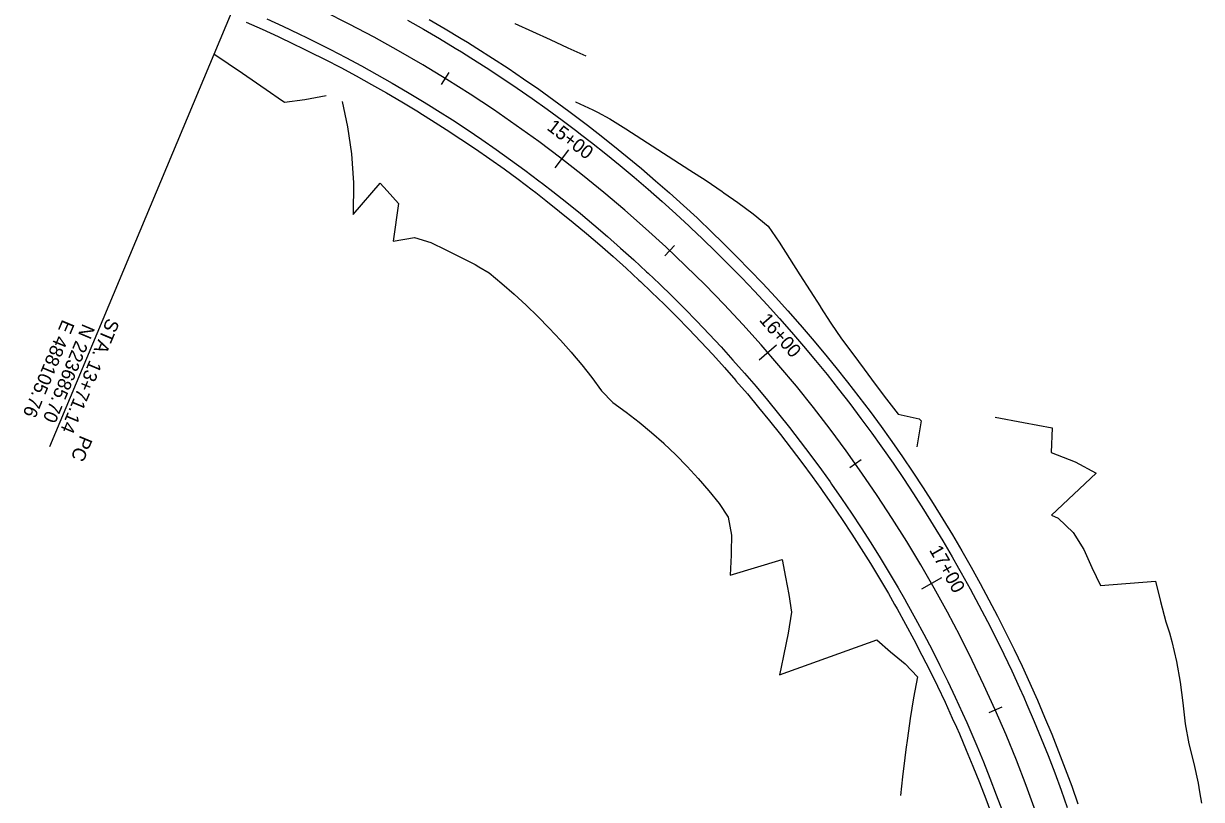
# Model space of a CAD drawing. Extents: x 487756 to 488722, y 222467 to 224000.
# Drawn here: x 488027.1 to 488442.7, y 223395.2 to 223669 of the extents above; entities that cross this region are included whole.
import ezdxf

# ---------------------------------------------------------------- set-up
doc = ezdxf.new("R2010")
doc.units = 0
for name, color, linetype in [('HM-SMOD-BRK LINE', 7, 'Continuous'), ('HR-FEAT-CUT', 7, 'Continuous'), ('HR-FEAT-EOR', 7, 'Continuous'), ('HR-FEAT-FILL', 7, 'Continuous'), ('HR-GMSC-HOR_VER ALN', 7, 'Continuous'), ('HR-GPLN-CL STA', 7, 'Continuous'), ('HR-GPLN-CL TICKS', 7, 'Continuous'), ('HR-GPLN-PCPT LDR', 7, 'Continuous'), ('HR-GPLN-PCPT TXT', 7, 'Continuous'), ('SV_MISC_MISC_TOPO', 7, 'Continuous')]:
    doc.layers.add(name, color=color, linetype=linetype)

msp = doc.modelspace()

# ---------------------------------------------------------------- linework, layer by layer
at = {"layer": 'HM-SMOD-BRK LINE'}
for points in [[(488112.92, 223670.6), (488118.58, 223668.02), (488124.21, 223665.36), (488127.22, 223663.91), (488129.8, 223662.64), (488135.35, 223659.84), (488140.87, 223656.97), (488146.35, 223654.04), (488151.8, 223651.03), (488157.21, 223647.95), (488162.57, 223644.81), (488167.9, 223641.59), (488170.02, 223640.29), (488173.18, 223638.31), (488178.43, 223634.97), (488183.63, 223631.55), (488188.78, 223628.08), (488193.89, 223624.53), (488198.96, 223620.92), (488203.98, 223617.25), (488208.95, 223613.51), (488210.24, 223612.52), (488213.87, 223609.71), (488218.75, 223605.85), (488223.58, 223601.92), (488228.35, 223597.94), (488233.08, 223593.89), (488237.75, 223589.79), (488242.37, 223585.62), (488246.94, 223581.4), (488247.5, 223580.88), (488251.45, 223577.12), (488255.91, 223572.78), (488260.31, 223568.39), (488264.66, 223563.94), (488268.95, 223559.44), (488273.18, 223554.88), (488277.35, 223550.26), (488281.4, 223545.67), (488281.47, 223545.6), (488285.52, 223540.88), (488289.51, 223536.12), (488293.45, 223531.3), (488297.32, 223526.43), (488301.13, 223521.51), (488304.88, 223516.55), (488308.56, 223511.53), (488311.63, 223507.26), (488312.18, 223506.48), (488315.73, 223501.37), (488319.22, 223496.22), (488322.65, 223491.03), (488326, 223485.79), (488329.29, 223480.51), (488332.52, 223475.2), (488335.67, 223469.83), (488337.86, 223466.01), (488338.76, 223464.43), (488341.78, 223459), (488344.72, 223453.52), (488347.6, 223448), (488350.41, 223442.45), (488353.15, 223436.87), (488355.81, 223431.25), (488358.41, 223425.6), (488359.85, 223422.36), (488360.93, 223419.91), (488363.38, 223414.19), (488365.76, 223408.44), (488368.06, 223402.67), (488370.29, 223396.86), (488372.44, 223391.03)], [(488162.56, 223670.22), (488168.21, 223667), (488173.82, 223663.72), (488179.38, 223660.36), (488181.59, 223659), (488184.9, 223656.93), (488190.38, 223653.44), (488195.82, 223649.87), (488201.2, 223646.23), (488206.54, 223642.53), (488211.84, 223638.76), (488217.08, 223634.92), (488222.28, 223631.01), (488223.63, 223629.98), (488227.43, 223627.04), (488232.52, 223623.01), (488237.56, 223618.91), (488242.55, 223614.74), (488247.49, 223610.51), (488252.37, 223606.22), (488257.2, 223601.87), (488261.98, 223597.46), (488262.56, 223596.91), (488266.69, 223592.99), (488271.35, 223588.45), (488275.95, 223583.86), (488280.49, 223579.21), (488284.97, 223574.51), (488289.4, 223569.74), (488293.76, 223564.92), (488297.99, 223560.12), (488298.06, 223560.05), (488302.29, 223555.12), (488306.47, 223550.14), (488310.58, 223545.1), (488314.62, 223540.01), (488318.61, 223534.88), (488322.52, 223529.69), (488326.37, 223524.45), (488329.58, 223519.98), (488330.15, 223519.16), (488333.87, 223513.83), (488337.51, 223508.45), (488341.09, 223503.02), (488344.6, 223497.55), (488348.04, 223492.03), (488351.4, 223486.47), (488354.7, 223480.87), (488356.99, 223476.88), (488357.93, 223475.23), (488361.08, 223469.55), (488364.16, 223463.82), (488367.17, 223458.06), (488370.1, 223452.26), (488372.96, 223446.42), (488375.75, 223440.55), (488378.46, 223434.64), (488379.97, 223431.26), (488381.1, 223428.7), (488383.66, 223422.73), (488386.14, 223416.72), (488388.55, 223410.68), (488390.88, 223404.62), (488393.13, 223398.52), (488395.3, 223392.39)]]:
    msp.add_lwpolyline(points, dxfattribs=at)
at = {"layer": 'HR-FEAT-CUT'}
for points in [[(488200.45, 223668.99), (488206.68, 223666.19), (488212.9, 223663.34), (488219.14, 223660.44), (488225.43, 223657.58)], [(488094.28, 223658.28), (488099.34, 223654.91), (488104.36, 223651.52), (488109.34, 223648.11), (488114.28, 223644.68), (488116.93, 223642.83), (488119.19, 223641.23), (488126.31, 223642.17), (488133.84, 223643.65)], [(488369.94, 223530.12), (488379.86, 223528.23), (488390.04, 223526.28), (488389.62, 223517.59), (488398.11, 223514.36), (488405.57, 223510.38), (488389.81, 223495.53), (488392.06, 223494.45), (488397.35, 223489.37), (488401.15, 223483.43), (488404.04, 223477.01), (488407.06, 223470.67), (488426.43, 223472.2), (488428.25, 223465.05), (488430.06, 223457.93), (488431.33, 223453.99), (488432.17, 223450.97), (488433.83, 223443.85), (488435.11, 223436.61), (488436.1, 223429.29), (488436.88, 223421.95), (488438.23, 223414.86), (488440, 223407.94), (488441.45, 223400.94), (488442, 223397.9), (488442.65, 223393.88)]]:
    msp.add_lwpolyline(points, dxfattribs=at)
at = {"layer": 'HR-FEAT-EOR'}
for points in [[(488170.21, 223670.47), (488175.86, 223667.16), (488181.47, 223663.77), (488183.7, 223662.4), (488187.03, 223660.32), (488192.56, 223656.79), (488198.03, 223653.2), (488203.46, 223649.53), (488208.85, 223645.8), (488214.18, 223642), (488219.47, 223638.13), (488224.7, 223634.2), (488226.06, 223633.16), (488229.89, 223630.19), (488235.02, 223626.13), (488240.11, 223621.99), (488245.14, 223617.8), (488250.11, 223613.54), (488255.03, 223609.21), (488259.9, 223604.83), (488264.71, 223600.38), (488265.3, 223599.83), (488269.46, 223595.87), (488274.16, 223591.3), (488278.79, 223586.68), (488283.37, 223581.99), (488287.89, 223577.25), (488292.35, 223572.44), (488296.74, 223567.59), (488301.01, 223562.75), (488301.07, 223562.67), (488305.34, 223557.71), (488309.55, 223552.68), (488313.69, 223547.61), (488317.77, 223542.48), (488321.78, 223537.3), (488325.73, 223532.08), (488329.61, 223526.8), (488332.84, 223522.29), (488333.42, 223521.47), (488337.16, 223516.09), (488340.84, 223510.67), (488344.44, 223505.2), (488347.98, 223499.69), (488351.44, 223494.13), (488354.84, 223488.53), (488358.16, 223482.88), (488360.47, 223478.86), (488361.41, 223477.19), (488364.59, 223471.46), (488367.7, 223465.7), (488370.73, 223459.89), (488373.68, 223454.04), (488376.57, 223448.16), (488379.37, 223442.24), (488382.11, 223436.29), (488383.63, 223432.88), (488384.76, 223430.3), (488387.34, 223424.28), (488389.85, 223418.23), (488392.27, 223412.14), (488394.62, 223406.03), (488396.89, 223399.88), (488399.08, 223393.71)], [(488105.64, 223669.44), (488111.29, 223666.95), (488116.9, 223664.39), (488122.48, 223661.76), (488125.46, 223660.31), (488128.02, 223659.05), (488133.53, 223656.28), (488139.01, 223653.43), (488144.44, 223650.52), (488149.84, 223647.54), (488155.21, 223644.49), (488160.53, 223641.37), (488165.81, 223638.18), (488167.91, 223636.89), (488171.05, 223634.93), (488176.25, 223631.61), (488181.41, 223628.22), (488186.52, 223624.77), (488191.59, 223621.26), (488196.62, 223617.68), (488201.6, 223614.03), (488206.53, 223610.33), (488207.81, 223609.35), (488211.41, 223606.56), (488216.25, 223602.73), (488221.03, 223598.84), (488225.77, 223594.88), (488230.46, 223590.87), (488235.09, 223586.8), (488239.67, 223582.67), (488244.2, 223578.48), (488244.76, 223577.96), (488248.68, 223574.24), (488253.1, 223569.93), (488257.47, 223565.58), (488261.78, 223561.16), (488266.03, 223556.7), (488270.23, 223552.17), (488274.37, 223547.6), (488278.39, 223543.04), (488278.45, 223542.97), (488282.47, 223538.3), (488286.43, 223533.57), (488290.33, 223528.79), (488294.17, 223523.96), (488297.95, 223519.08), (488301.67, 223514.16), (488305.32, 223509.19), (488308.36, 223504.94), (488308.91, 223504.17), (488312.44, 223499.11), (488315.9, 223494), (488319.29, 223488.85), (488322.62, 223483.66), (488325.89, 223478.42), (488329.08, 223473.14), (488332.21, 223467.83), (488334.39, 223464.04), (488335.27, 223462.47), (488338.27, 223457.08), (488341.19, 223451.65), (488344.04, 223446.18), (488346.83, 223440.67), (488349.54, 223435.13), (488352.19, 223429.56), (488354.76, 223423.95), (488356.19, 223420.74), (488357.26, 223418.31), (488359.69, 223412.64), (488362.05, 223406.94), (488364.33, 223401.21), (488366.54, 223395.45), (488368.68, 223389.66)]]:
    msp.add_lwpolyline(points, dxfattribs=at)
at = {"layer": 'HR-FEAT-FILL'}
for points in [[(488139.56, 223641.54), (488141.45, 223632.57), (488142.8, 223623.01), (488143.53, 223612.78), (488143.44, 223601.62), (488152.9, 223612.63), (488155.35, 223609.98), (488159.35, 223605.5), (488157.46, 223592.24), (488165.08, 223593.44), (488170.81, 223591.7), (488176.05, 223589.2), (488181.25, 223586.6), (488186.41, 223583.92), (488187.75, 223583.2), (488191.42, 223580.99), (488195.85, 223577.32), (488200.19, 223573.53), (488204.42, 223569.63), (488208.56, 223565.62), (488212.58, 223561.51), (488216.51, 223557.29), (488220.32, 223552.98), (488220.78, 223552.44), (488224.02, 223548.57), (488227.6, 223544.06), (488231.01, 223539.4), (488234.98, 223535.32), (488239.68, 223531.92), (488244.25, 223528.37), (488248.7, 223524.67), (488252.96, 223520.9), (488253.03, 223520.84), (488257.21, 223516.86), (488261.26, 223512.75), (488265.16, 223508.51), (488268.92, 223504.13), (488272.52, 223499.64), (488275.75, 223494.86), (488276.82, 223488.52), (488276.75, 223482.53), (488276.71, 223481.44), (488276.4, 223474.35), (488294.76, 223479.87), (488295.97, 223473.69), (488297.06, 223467.49), (488298.01, 223461.29), (488296.82, 223453.88), (488295.36, 223446.45), (488294.3, 223441.27), (488293.82, 223439.13), (488328.09, 223451.51), (488332.93, 223447.27), (488338.09, 223443.12), (488342.51, 223438.52), (488341.13, 223431.08), (488339.91, 223423.83), (488338.93, 223416.81), (488338.41, 223412.87), (488338.03, 223409.93), (488337.2, 223403.17), (488336.45, 223396.55)], [(488221.86, 223641.35), (488227.99, 223638.51), (488229.59, 223637.75), (488233.93, 223635.36), (488239.6, 223631.83), (488245.26, 223628.25), (488250.86, 223624.57), (488256.54, 223620.95), (488262.22, 223617.29), (488267.89, 223613.58), (488273.52, 223609.78), (488274.21, 223609.31), (488279.08, 223605.88), (488284.51, 223601.81), (488289.77, 223597.54), (488293.65, 223591.9), (488297.34, 223586.13), (488301.01, 223580.38), (488304.65, 223574.66), (488308.23, 223569.04), (488308.28, 223568.95), (488311.9, 223563.27), (488315.71, 223557.78), (488319.67, 223552.42), (488323.62, 223547.07), (488327.57, 223541.73), (488331.58, 223536.44), (488335.62, 223531.16), (488343.08, 223529.55), (488343.76, 223528.77), (488342.27, 223519.6)]]:
    msp.add_lwpolyline(points, dxfattribs=at)
at = {"layer": 'HR-GMSC-HOR_VER ALN'}
msp.add_arc((487912.68, 223224.48), 500, 355.8619, 67.2843, dxfattribs=at)
at = {"layer": 'HR-GPLN-CL TICKS'}
for points in [[(488177.12, 223651.77), (488174.49, 223647.52)], [(488219.37, 223624.43), (488214.5, 223618.08)], [(488256.74, 223590.72), (488253.32, 223587.07)], [(488292.71, 223555.52), (488286.68, 223550.27)], [(488322.64, 223515.06), (488318.56, 223512.17)], [(488350.91, 223473.42), (488343.95, 223469.47)], [(488372.2, 223427.82), (488367.63, 223425.8)]]:
    msp.add_lwpolyline(points, dxfattribs=at)
at = {"layer": 'HR-GPLN-PCPT LDR'}
msp.add_lwpolyline([(488105.76, 223685.7), (488036.25, 223519.66)], dxfattribs=at)
at = {"layer": 'SV_MISC_MISC_TOPO'}
for p, q in [((488200.45, 223668.99), (488200.45, 223668.99)), ((488206.68, 223666.19), (488206.68, 223666.19)), ((488212.9, 223663.34), (488212.9, 223663.34)), ((488094.28, 223658.28), (488094.28, 223658.28)), ((488219.14, 223660.44), (488219.14, 223660.44)), ((488225.43, 223657.58), (488225.43, 223657.58)), ((488099.34, 223654.91), (488099.34, 223654.91)), ((488104.36, 223651.52), (488104.36, 223651.52)), ((488109.34, 223648.11), (488109.34, 223648.11)), ((488114.28, 223644.68), (488114.28, 223644.68)), ((488116.93, 223642.83), (488116.93, 223642.83)), ((488119.19, 223641.23), (488119.19, 223641.23)), ((488126.31, 223642.17), (488126.31, 223642.17)), ((488133.84, 223643.65), (488133.84, 223643.65)), ((488139.56, 223641.54), (488139.56, 223641.54)), ((488221.86, 223641.35), (488221.86, 223641.35)), ((488227.99, 223638.51), (488227.99, 223638.51)), ((488229.59, 223637.75), (488229.59, 223637.75)), ((488141.45, 223632.57), (488141.45, 223632.57)), ((488233.93, 223635.36), (488233.93, 223635.36)), ((488239.6, 223631.83), (488239.6, 223631.83)), ((488245.26, 223628.25), (488245.26, 223628.25)), ((488250.86, 223624.57), (488250.86, 223624.57)), ((488142.8, 223623.01), (488142.8, 223623.01)), ((488256.54, 223620.95), (488256.54, 223620.95)), ((488262.22, 223617.29), (488262.22, 223617.29)), ((488143.53, 223612.78), (488143.53, 223612.78)), ((488152.9, 223612.63), (488152.9, 223612.63)), ((488267.89, 223613.58), (488267.89, 223613.58)), ((488155.35, 223609.98), (488155.35, 223609.98)), ((488273.52, 223609.78), (488273.52, 223609.78)), ((488274.21, 223609.31), (488274.21, 223609.31)), ((488159.35, 223605.5), (488159.35, 223605.5)), ((488279.08, 223605.88), (488279.08, 223605.88)), ((488143.44, 223601.62), (488143.44, 223601.62)), ((488284.51, 223601.81), (488284.51, 223601.81)), ((488289.77, 223597.54), (488289.77, 223597.54)), ((488157.46, 223592.24), (488157.46, 223592.24)), ((488165.08, 223593.44), (488165.08, 223593.44)), ((488170.81, 223591.7), (488170.81, 223591.7)), ((488293.65, 223591.9), (488293.65, 223591.9)), ((488176.05, 223589.2), (488176.05, 223589.2)), ((488181.25, 223586.6), (488181.25, 223586.6)), ((488186.41, 223583.92), (488186.41, 223583.92)), ((488187.75, 223583.2), (488187.75, 223583.2)), ((488297.34, 223586.13), (488297.34, 223586.13)), ((488191.42, 223580.99), (488191.42, 223580.99)), ((488301.01, 223580.38), (488301.01, 223580.38)), ((488195.85, 223577.32), (488195.85, 223577.32)), ((488304.65, 223574.66), (488304.65, 223574.66)), ((488200.19, 223573.53), (488200.19, 223573.53)), ((488204.42, 223569.63), (488204.42, 223569.63)), ((488208.56, 223565.62), (488208.56, 223565.62)), ((488308.23, 223569.04), (488308.23, 223569.04)), ((488308.28, 223568.95), (488308.28, 223568.95)), ((488212.58, 223561.51), (488212.58, 223561.51)), ((488311.9, 223563.27), (488311.9, 223563.27)), ((488216.51, 223557.29), (488216.51, 223557.29)), ((488315.71, 223557.78), (488315.71, 223557.78)), ((488220.32, 223552.98), (488220.32, 223552.98)), ((488220.78, 223552.44), (488220.78, 223552.44)), ((488319.67, 223552.42), (488319.67, 223552.42)), ((488224.02, 223548.57), (488224.02, 223548.57)), ((488323.62, 223547.07), (488323.62, 223547.07)), ((488227.6, 223544.06), (488227.6, 223544.06)), ((488327.57, 223541.73), (488327.57, 223541.73)), ((488231.01, 223539.4), (488231.01, 223539.4)), ((488234.98, 223535.32), (488234.98, 223535.32)), ((488331.58, 223536.44), (488331.58, 223536.44)), ((488239.68, 223531.92), (488239.68, 223531.92)), ((488244.25, 223528.37), (488244.25, 223528.37)), ((488335.62, 223531.16), (488335.62, 223531.16)), ((488343.08, 223529.55), (488343.08, 223529.55)), ((488343.76, 223528.77), (488343.76, 223528.77)), ((488369.94, 223530.12), (488369.94, 223530.12)), ((488379.86, 223528.23), (488379.86, 223528.23)), ((488248.7, 223524.67), (488248.7, 223524.67)), ((488390.04, 223526.28), (488390.04, 223526.28)), ((488252.96, 223520.9), (488252.96, 223520.9)), ((488253.03, 223520.84), (488253.03, 223520.84)), ((488257.21, 223516.86), (488257.21, 223516.86)), ((488342.27, 223519.6), (488342.27, 223519.6)), ((488389.62, 223517.59), (488389.62, 223517.59)), ((488261.26, 223512.75), (488261.26, 223512.75)), ((488398.11, 223514.36), (488398.11, 223514.36)), ((488265.16, 223508.51), (488265.16, 223508.51)), ((488405.57, 223510.38), (488405.57, 223510.38)), ((488268.92, 223504.13), (488268.92, 223504.13)), ((488272.52, 223499.64), (488272.52, 223499.64)), ((488389.81, 223495.53), (488389.81, 223495.53)), ((488275.75, 223494.86), (488275.75, 223494.86)), ((488392.06, 223494.45), (488392.06, 223494.45)), ((488276.82, 223488.52), (488276.82, 223488.52)), ((488397.35, 223489.37), (488397.35, 223489.37)), ((488276.75, 223482.53), (488276.75, 223482.53)), ((488401.15, 223483.43), (488401.15, 223483.43)), ((488276.71, 223481.44), (488276.71, 223481.44)), ((488294.76, 223479.87), (488294.76, 223479.87)), ((488276.4, 223474.35), (488276.4, 223474.35)), ((488404.04, 223477.01), (488404.04, 223477.01)), ((488295.97, 223473.69), (488295.97, 223473.69)), ((488407.06, 223470.67), (488407.06, 223470.67)), ((488426.43, 223472.2), (488426.43, 223472.2)), ((488297.06, 223467.49), (488297.06, 223467.49)), ((488428.25, 223465.05), (488428.25, 223465.05)), ((488298.01, 223461.29), (488298.01, 223461.29)), ((488430.06, 223457.93), (488430.06, 223457.93)), ((488296.82, 223453.88), (488296.82, 223453.88)), ((488431.33, 223453.99), (488431.33, 223453.99)), ((488328.09, 223451.51), (488328.09, 223451.51)), ((488432.17, 223450.97), (488432.17, 223450.97)), ((488295.36, 223446.45), (488295.36, 223446.45)), ((488332.93, 223447.27), (488332.93, 223447.27)), ((488294.3, 223441.27), (488294.3, 223441.27)), ((488338.09, 223443.12), (488338.09, 223443.12)), ((488433.83, 223443.85), (488433.83, 223443.85)), ((488293.82, 223439.13), (488293.82, 223439.13)), ((488342.51, 223438.52), (488342.51, 223438.52)), ((488435.11, 223436.61), (488435.11, 223436.61)), ((488341.13, 223431.08), (488341.13, 223431.08)), ((488436.1, 223429.29), (488436.1, 223429.29)), ((488339.91, 223423.83), (488339.91, 223423.83)), ((488436.88, 223421.95), (488436.88, 223421.95)), ((488338.93, 223416.81), (488338.93, 223416.81)), ((488338.41, 223412.87), (488338.41, 223412.87)), ((488438.23, 223414.86), (488438.23, 223414.86)), ((488338.03, 223409.93), (488338.03, 223409.93)), ((488440, 223407.94), (488440, 223407.94)), ((488337.2, 223403.17), (488337.2, 223403.17)), ((488441.45, 223400.94), (488441.45, 223400.94)), ((488336.45, 223396.55), (488336.45, 223396.55)), ((488442, 223397.9), (488442, 223397.9))]:
    msp.add_line(p, q, dxfattribs=at)

# ---------------------------------------------------------------- texts
at = {"layer": 'HR-GPLN-CL STA'}
for s, rotation, p in [('15+00', 322.5178, (488211.45, 223631.76)), ('16+00', 311.0586, (488286.41, 223564.28)), ('17+00', 299.5995, (488346.47, 223483.26))]:
    msp.add_text(s, height=4.8, rotation=rotation, dxfattribs=at).set_placement(p)
at = {"layer": 'HR-GPLN-PCPT TXT'}
for s, p in [('E 488105.76', (488040.85, 223564.82)), ('N 223685.70', (488048.03, 223563.35)), ('STA. 13+71.14', (488056.66, 223565.32)), ('PC ', (488047.16, 223523.97))]:
    msp.add_text(s, height=4.8, rotation=247.2843, dxfattribs=at).set_placement(p)

doc.saveas('drawing.dxf')
